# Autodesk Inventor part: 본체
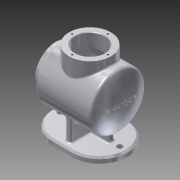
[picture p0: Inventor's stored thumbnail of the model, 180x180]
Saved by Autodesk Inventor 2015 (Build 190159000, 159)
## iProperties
Created: 2016-04
Part Number: 본체
Material: 알루미늄 6061
Document SubType Name: Modeling
Designer: Administrator
Density: 2.7 g/cm^3
Appearance: 알루미늄 - 평지
Mass: 914.938 g
Surface Area: 1241.05 cm^2
Volume: 338.866 cm^3
Author: Administrator
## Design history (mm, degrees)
sketch "스케치1"
  geometry: L1 (-17.5, 50)-(17.5, 50); L2 (17.5, -50)-(-17.5, -50); L3 (0, 50)-(0, -50); C1 r 5 at (54, 0); C2 r 5 at (-54, 0); A1 r 50 centre (-17.5, 0) between (-17.5, 50) and (-17.5, -50); A2 r 50 centre (17.5, 0) between (17.5, -50) and (17.5, 50)
  constraints: 6 end point, 4 centre point, 4 point on circle, 4 tangent, 2 midpoint, 1 horizontal, 1 parallel
  dimensions: "d3" = 10 diameter of C1; "d4" = 10 diameter of C2; "d5" = 54 distance from line of L3 C2.centre; "d6" = 54 distance from line of C1.centre L3
extrude "돌출1" new body sketch "스케치1" distance "d7" = 10; taper "d8" = 0 deg
chamfer "모따기1" distance "d9" = 3; stored, may be unused: second distance "d10" = 2, angle "d11" = 45 deg
sketch "스케치2"
  geometry: C1 r 50 at (0, 79); 1 further point
  constraints: 1 centre point, 1 vertical alignment
  dimensions: "d12" = 100 diameter of C1; "d13" = 79 distance of point (0, 0) C1.centre
extrude "돌출2" join sketch "스케치2" stored distance "d14" = 100; taper "d15" = 0 deg
sketch "스케치3"
  geometry: C1 r 50 at (0, 0) reference; C2 r 38 at (0, 0); 1 further point
  constraints: 1 centre point, 1 coincident
  dimensions: "d16" = 76 diameter of C2
extrude "돌출3" join sketch "스케치3" distance "d17" = 12; taper "d18" = 0 deg
sketch "스케치4"
  geometry: L1 (50, 29)-(50, 129) reference; L2 (-50, 129)-(-50, 29) reference; L3 (62, 41)-(62, 117) reference; L4 (-50, 79)-(-60, 79); L5 (-50, 129)-(-50, 79); A1 r 120 centre (59.983, 81.003) between (-50, 129) and (-60, 79); 1 further point
  constraints: 4 end point, 3 point on circle, 1 centre point, 1 collinear, 1 horizontal, 1 midpoint
  dimensions: "d22" = 120 radius of A1
revolve "회전1" sketch "스케치4" stored, may be unused: angle "d23" = 90 deg
fillet "모깎기2" dims "d24" = 5
fillet "모깎기3" dims "d25" = 5
node "작업 평면1"
sketch "스케치5"
  geometry: C1 r 38 at (0, 0); 1 further point
  constraints: 1 centre point, 1 coincident
  dimensions: "d27" = 76 diameter of C1
extrude "돌출4" join sketch "스케치5" stored distance "d28" = 12; taper "d29" = 0 deg
sketch "스케치6"
  geometry: C1 r 38 at (0, 0) reference; C2 r 27 at (0, 0); 1 further point
  constraints: 1 centre point, 1 coincident
  dimensions: "d30" = 54 diameter of C2
extrude "돌출5" cut sketch "스케치6" distance "d31" = 15; taper "d32" = 0 deg
sketch "스케치7"
  geometry: C1 r 47 at (0, 79); 2 further points
  constraints: 1 centre point, 1 vertical alignment
  dimensions: "d92" = 94 diameter of C1
extrude "돌출6" cut sketch "스케치7" stored distance "d34" = 94; taper "d35" = 0 deg
sketch "스케치9"
  geometry: L1 (-47, 79)-(-57, 79); L2 (-47, 125.869)-(-48.072, 125.869); L3 (-47, 125.869)-(-47, 79); A1 r 120 centre (59.983, 81.003) between (-51.314, 125.869) and (-60.017, 81.003) reference; A2 r 117 centre (59.983, 81.003) between (-48.072, 125.869) and (-57, 79); A3 r 120 centre (59.983, 81.003) between (-60.017, 81.003) and (-60, 79) reference; 1 further point
  constraints: 6 end point, 2 horizontal, 2 point on circle, 1 centre point
revolve "회전2" sketch "스케치9" stored, may be unused: angle "d36" = 90 deg
fillet "모깎기4" dims "d37" = 2
sketch "스케치10"
  geometry: C1 r 38 at (0, 0) reference; C2 r 27 at (0, 0)
  constraints: 1 centre point, 1 coincident
  dimensions: "d38" = 54 diameter of C2
extrude "돌출7" cut sketch "스케치10" stored distance "d39" = 94; taper "d40" = 0 deg
fillet "모깎기5" dims "d41" = 3
chamfer "모따기2" distance "d42" = 1; stored, may be unused: second distance "d43" = 2, angle "d44" = 45 deg
sketch "스케치11"
  geometry: L1 (-5, 40)-(5, 40); L2 (5, 40)-(5, -40); L3 (5, -40)-(-5, -40); L4 (-5, -40)-(-5, 40); A1 r 47 centre (17.5, 0) between (17.5, -47) and (17.5, 47) reference; 2 further points
  constraints: 8 end point, 2 parallel, 1 horizontal, 1 horizontal alignment, 1 midpoint, 1 perpendicular
  dimensions: "d45" = 10 distance of L2.end L3.end; "d46" = 80 distance of L1.end L2.end; "d47" = 5 distance from line of L4 point (0, 0)
extrude "돌출8" join sketch "스케치11" stored distance "d48" = 94; taper "d49" = 0 deg
sketch "스케치12"
  geometry: L1 (36.65, 29)-(40, 10); L2 (-36.65, 29)-(-40, 10); 1 further point
  constraints: 4 end point
  dimensions: "d50" = 40 horizontal distance of point (0, 0) L1.end; "d52" = 40 horizontal distance of L2.end point (0, 0)
feature "리브1" dims "d54" = 1, "d55" = 10, "d56" = 0, "d57" = 0, "d58" = 1, "d59" = 1
feature "리브2" dims "d60" = 1, "d61" = 10, "d62" = 0, "d63" = 0, "d64" = 1, "d65" = 1
sketch "스케치13"
  geometry: C1 r 28 at (0, 0) reference; 2 further points
  constraints: 1 horizontal alignment
  dimensions: "d66" = 32.5 distance of C1.centre point (32.5, 0)
hole "구멍1" sketch "스케치13" at (32.5, 0) diameter "d67" = 3.242; stored, may be unused: countersink angle "d71" = 90 deg, drill point angle "d73" = 118 deg; dims "d68" = 8, "d69" = 4, "d70" = 2, "d72" = 10
sketch "스케치14"
  geometry: C1 r 38 at (0, 0) reference; 1 further point
  constraints: 1 vertical alignment
  dimensions: "d77" = 32.5 distance of C1.centre point (0, 32.5)
hole "구멍2" sketch "스케치14" at (0, 32.5) diameter "d78" = 3.242; stored, may be unused: countersink angle "d82" = 90 deg, drill point angle "d84" = 118 deg; dims "d79" = 8, "d80" = 4, "d81" = 2, "d83" = 10
node "작업 평면2"
sketch "스케치15"
  geometry: C1 r 38 at (0, 79) reference; 2 further points
  constraints: 2 coincident, 1 other
feature "엠보싱1" sketch "스케치15" dims "d3" = 10, "d4" = 10, "d5" = 54, "d6" = 54, "d89" = 0.5, "d90" = 0
fillet "모깎기6" dims "d91" = 3
fillet "모깎기7" dims "d93" = 2
node "솔리드1"
pattern_circular "원형 패턴1" dims angle "d75" = 360 deg
pattern_circular "원형 패턴2" dims angle "d86" = 360 deg
node "투영된 루프1"
other parameters: "d26" = -144
